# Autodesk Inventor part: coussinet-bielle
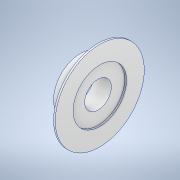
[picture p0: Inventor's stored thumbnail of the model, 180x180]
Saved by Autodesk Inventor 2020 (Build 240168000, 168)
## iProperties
Created: 2023-10
Part Number: coussinet-bielle
Material: Aluminium 6061
Document SubType Name: Modeling
Designer: bruno
Density: 2.7 g/cm^3
Appearance: Aluminium - Plat
Author: bruno
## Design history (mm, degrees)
sketch "Esquisse1"
  geometry: C1 r 3 at (0, 0); C2 r 1.5 at (0, 0); 1 further point
  constraints: 2 centre point, 2 coincident
  dimensions: "d0" = 6 diameter of C1; "d1" = 3 diameter of C2
extrude "Extrusion1" new body sketch "Esquisse1" distance "d2" = 2; taper "d3" = 0 deg
sketch "Esquisse2"
  geometry: C1 r 1.5 at (0, 0) reference; C2 r 5 at (0, 0); 1 further point
  constraints: 1 centre point, 1 coincident
  dimensions: "d4" = 10 diameter of C2
extrude "Extrusion2" join sketch "Esquisse2" distance "d5" = 0.2; taper "d6" = 0 deg
sketch "Esquisse3"
  geometry: C1 r 1.5 at (0, 0) reference; C2 r 3 at (0, 0); 1 further point
  constraints: 1 centre point, 1 coincident
extrude "Extrusion3" cut sketch "Esquisse3" distance "d7" = 0.2; taper "d8" = 0 deg
node "Solide1"
